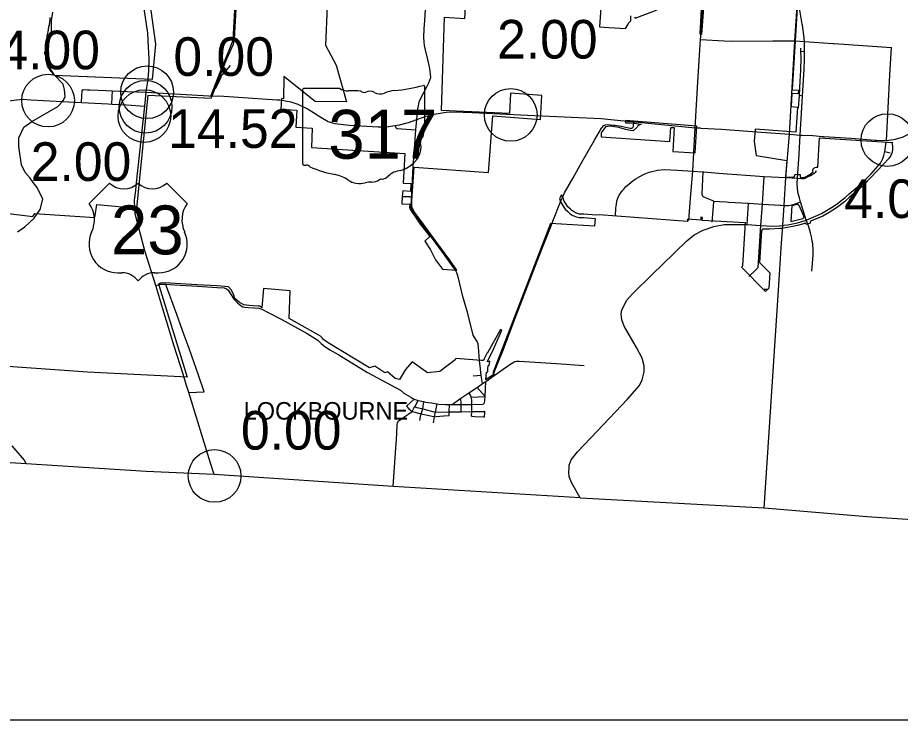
# Model space of a CAD drawing. Extents: x 1729596 to 1934326, y 644115 to 911751.
# Drawn here: x 1824362 to 1849496, y 650175 to 670183 of the extents above; entities that cross this region are included whole.
import ezdxf

# ---------------------------------------------------------------- set-up
doc = ezdxf.new("R2010")
doc.units = 0
for name, color, linetype in [('Default', 7, 'Continuous'), ('GM_X_City_Street', 7, 'Continuous'), ('GM_X_Corporation', 7, 'Continuous'), ('GM_X_Corporation_Text', 7, 'Continuous'), ('GM_X_County', 7, 'Continuous'), ('GM_X_County_Road', 7, 'Continuous'), ('GM_X_State_Route', 7, 'Continuous'), ('GM_X_State_Shield', 7, 'Continuous'), ('GM_X_Township', 7, 'Continuous'), ('GM_X_Township_Road', 7, 'Continuous'), ('GM_X_US_Route', 7, 'Continuous'), ('GM_X_US_Shield', 7, 'Continuous'), ('SC_Scratch1', 7, 'Continuous')]:
    doc.layers.add(name, color=color, linetype=linetype)

msp = doc.modelspace()

# ---------------------------------------------------------------- linework, layer by layer
at = {"layer": 'Default'}
for centre in [(1828047, 668059), (1825227, 667820), (1828004, 667646), (1827970, 667382), (1838401, 667414), (1849129, 666698), (1829970, 657133), (1829970, 657133)]:
    msp.add_circle(centre, 750, dxfattribs=at)
at = {"layer": 'GM_X_City_Street'}
for points in [[(1843656, 667049), (1843730, 668355), (1843808, 669565), (1843821, 669743)], [(1843808, 669565), (1844483, 669519), (1844695, 669514), (1845864, 669519), (1846450, 669518)], [(1846766, 669501), (1847577, 669446), (1847609, 669443)], [(1847609, 669443), (1849242, 669337)], [(1849099, 666688), (1849197, 668542), (1849242, 669337)], [(1839885, 665084), (1839885, 665085), (1839936, 665199), (1840176, 665624), (1840428, 666065), (1840789, 666690), (1840989, 667035), (1841055, 667112), (1841091, 667132), (1841160, 667140), (1841329, 667121)], [(1841329, 667121), (1841331, 667121), (1841362, 667118), (1841548, 667090), (1841804, 667034), (1841850, 667040), (1841888, 667054), (1841901, 667094), (1841906, 667217)], [(1846817, 664417), (1846817, 664417), (1846650, 664934), (1846620, 665052), (1846589, 665176), (1846576, 665245), (1846564, 665323), (1846559, 665448), (1846566, 665612), (1846612, 666291), (1846640, 666840)], [(1848969, 666119), (1848995, 666171), (1849029, 666256), (1849053, 666371), (1849069, 666502), (1849090, 666636)], [(1843475, 664407), (1843521, 665040), (1843585, 665813), (1843616, 666340), (1843616, 666350)], [(1849053, 666371), (1849205, 666333)], [(1847754, 664925), (1847924, 665066), (1848036, 665165), (1848377, 665454), (1848662, 665739), (1848862, 665965), (1848928, 666037), (1848969, 666119)], [(1841382, 664543), (1841399, 664762), (1841410, 664876), (1841424, 664962), (1841449, 665044), (1841489, 665125), (1841589, 665265), (1841622, 665300), (1841682, 665373), (1841763, 665445), (1841876, 665541), (1841950, 665588), (1842030, 665633), (1842044, 665642), (1842201, 665725), (1842346, 665782), (1842578, 665838), (1842779, 665860), (1843152, 665838), (1843585, 665813)], [(1843585, 665813), (1843884, 665790), (1843899, 665789)], [(1846566, 665612), (1846682, 665605), (1846753, 665606), (1846788, 665616), (1846809, 665625), (1846876, 665657), (1846937, 665690), (1846981, 665717), (1847038, 665750), (1847077, 665776), (1847110, 665825)], [(1844182, 664943), (1844183, 664956), (1843899, 665072), (1843876, 665090), (1843858, 665121), (1843856, 665165), (1843884, 665790)], [(1843899, 665789), (1844317, 665758)], [(1844317, 665758), (1845623, 665660), (1846239, 665629), (1846252, 665628)], [(1845180, 662812), (1845373, 662988), (1845449, 663072), (1845481, 663663), (1845515, 664119), (1845524, 664265), (1845568, 664872), (1845623, 665660)], [(1846252, 665628), (1846566, 665612)], [(1839549, 664258), (1839549, 664258), (1839599, 664384), (1839820, 664942), (1839841, 664989)], [(1844141, 664364), (1844165, 664687), (1844173, 664813), (1844182, 664943)], [(1844183, 664956), (1844349, 664944), (1844545, 664934)], [(1844545, 664934), (1844603, 664931), (1845177, 664896), (1845568, 664872), (1846075, 664842), (1846096, 664841)], [(1845136, 664293), (1845177, 664896)], [(1846096, 664841), (1846187, 664837), (1846309, 664831), (1846457, 664867), (1846650, 664934)], [(1846817, 664417), (1847083, 664527), (1847247, 664603), (1847588, 664806), (1847736, 664910), (1847754, 664925)], [(1846184, 664272), (1846281, 664286), (1846389, 664307), (1846430, 664315)], [(1846430, 664315), (1846528, 664335), (1846662, 664370), (1846817, 664417)], [(1846845, 664350), (1846817, 664417)], [(1845083, 664290), (1845136, 664289)], [(1845136, 664293), (1845524, 664265), (1845535, 664264)], [(1845535, 664264), (1845681, 664255), (1845825, 664250), (1846053, 664255), (1846149, 664267), (1846184, 664272)], [(1845481, 663663), (1845535, 663659)], [(1837539, 660181), (1837510, 660425), (1837488, 660804), (1837473, 660888), (1837445, 660962), (1837363, 661097), (1837334, 661143), (1837179, 661755), (1837041, 662240), (1836911, 662767)], [(1845621, 662454), (1845730, 662447)], [(1837596, 659765), (1837560, 659995), (1837541, 660163), (1837539, 660181)], [(1837560, 659995), (1837334, 659976)], [(1837635, 659187), (1837659, 659225), (1837665, 659283), (1837670, 659391), (1837689, 659827)], [(1835769, 659280), (1835932, 659249), (1835976, 659238), (1836143, 659213), (1836308, 659188), (1836352, 659181), (1836539, 659172), (1836658, 659169), (1836730, 659167), (1836917, 659304), (1836983, 659348), (1837212, 659501), (1837429, 659645), (1837445, 659656), (1837596, 659765)], [(1837670, 659391), (1837445, 659656)], [(1835149, 658156), (1835173, 658586), (1835178, 658644), (1835198, 658690), (1835228, 658716), (1835388, 658822), (1835503, 658898), (1835594, 658965), (1835647, 659068), (1835667, 659101), (1835765, 659280), (1835769, 659280)], [(1835431, 659119), (1835651, 659324)], [(1835571, 659367), (1835611, 659343), (1835651, 659324), (1835705, 659300), (1835765, 659280)], [(1836986, 659182), (1836986, 659182), (1836983, 659348)], [(1837293, 659205), (1837293, 659298), (1837275, 659375), (1837255, 659430), (1837212, 659501)], [(1837275, 659375), (1837670, 659391)], [(1835431, 659119), (1835501, 659049), (1835594, 658965)], [(1835667, 659101), (1835727, 659083), (1835872, 659050)], [(1835847, 658874), (1835854, 658904), (1835895, 659045), (1835932, 659249)], [(1835872, 659050), (1835895, 659045), (1836247, 658952), (1836260, 658952), (1836272, 658952), (1836650, 658957), (1836651, 658957)], [(1836244, 658873), (1836260, 658952), (1836308, 659188)], [(1836645, 658855), (1836650, 658957), (1836658, 659169)], [(1836730, 659167), (1836986, 659169), (1837283, 659172), (1837284, 659172)], [(1836990, 658961), (1836986, 659169), (1836986, 659182)], [(1837284, 659172), (1837293, 659172), (1837595, 659175), (1837635, 659187)], [(1837289, 658839), (1837291, 658965), (1837292, 659041), (1837293, 659172), (1837293, 659204), (1837293, 659205)], [(1835594, 658965), (1835854, 658904), (1836211, 658826), (1836233, 658821), (1836279, 658824)], [(1835811, 658713), (1835846, 658870), (1835847, 658874)], [(1836201, 658642), (1836233, 658821), (1836240, 658855), (1836244, 658873)], [(1836279, 658824), (1836489, 658841), (1836508, 658843)], [(1836508, 658843), (1836645, 658855)], [(1836651, 658957), (1836990, 658961), (1837283, 658965), (1837284, 658965)], [(1837284, 658965), (1837291, 658965), (1837654, 658970)], [(1837289, 658839), (1837307, 658831), (1837377, 658823), (1837627, 658812), (1837653, 658816)], [(1837653, 658816), (1837657, 658830), (1837666, 658934), (1837660, 658964), (1837654, 658970)]]:
    msp.add_lwpolyline(points, dxfattribs=at)
at = {"layer": 'GM_X_Corporation'}
for points in [[(1833173, 670502), (1833129, 669403), (1833432, 668828), (1833725, 667789), (1832832, 667797), (1831945, 668503), (1831927, 667875), (1831874, 667878), (1831856, 667578), (1832313, 667551), (1832283, 667067), (1832752, 667038), (1832725, 666484), (1835390, 666313), (1835341, 665474), (1835554, 665456), (1835544, 665236), (1835325, 665251), (1835312, 665101), (1835531, 665087), (1835531, 665067), (1835311, 665081), (1835298, 664882), (1835526, 664868), (1835524, 664780), (1835526, 664761), (1835534, 664732), (1835571, 664680), (1835694, 664503), (1835826, 664305), (1835933, 664158), (1836095, 663953), (1835954, 663820), (1836119, 663570), (1836264, 663286), (1836455, 663025), (1836867, 662988), (1836671, 663278), (1836402, 663637), (1836133, 663996), (1835831, 664420), (1835664, 664648), (1835602, 664750), (1835586, 664820), (1835588, 664971), (1835652, 665922), (1837770, 665776), (1837890, 667386), (1839249, 667283), (1839283, 667963), (1838398, 668037), (1838370, 667454), (1836435, 667543), (1836512, 670195), (1837091, 670161), (1837244, 672782)], [(1841095, 672208), (1840928, 669924), (1841193, 669907), (1841670, 669872), (1841733, 669978), (1841760, 670027), (1841820, 670091), (1841822, 670234)], [(1827964, 671763), (1828287, 669430), (1828195, 668421), (1825415, 668535), (1825343, 668623), (1825317, 668649), (1825215, 668803), (1825206, 668828), (1825206, 668854), (1825172, 668956), (1825164, 668982), (1825164, 669084), (1825138, 669161), (1825138, 669186), (1825164, 669263), (1825155, 669289), (1825155, 669340), (1825172, 669365), (1825172, 669442), (1825189, 669493), (1825189, 669587), (1825198, 669613), (1825198, 669664), (1825224, 669741), (1825232, 669775), (1825232, 669800), (1825241, 669826), (1825241, 669877), (1825249, 669903), (1825249, 669928), (1825266, 669980), (1825266, 670005), (1825275, 670031), (1825275, 670082), (1825283, 670107), (1825283, 670133), (1825292, 670159), (1825292, 670184)], [(1823170, 664722), (1824798, 664523), (1824853, 664602), (1826558, 664497), (1826621, 664858), (1827759, 664757), (1828076, 667971), (1829875, 667888), (1829895, 667927), (1829974, 668145), (1830178, 668652), (1830316, 669014), (1830507, 669429), (1830540, 669567), (1830589, 670604)], [(1843847, 670779), (1843787, 669720), (1843847, 669716), (1843911, 670587)], [(1846554, 670450), (1846417, 668127), (1846599, 668118), (1846591, 668018), (1846408, 668027), (1846388, 667649), (1846569, 667637), (1846519, 666923), (1845364, 667003), (1845334, 666654), (1845390, 666258), (1846262, 666117), (1846226, 665648), (1846429, 665637), (1846458, 665637), (1846476, 665647), (1846487, 665681), (1846501, 665723), (1846566, 665719), (1846641, 665713), (1846639, 665643), (1846659, 665639), (1846749, 665636), (1846781, 665639), (1846936, 665727), (1846970, 665757), (1847013, 665789), (1847006, 665816), (1847008, 665855), (1847017, 665876), (1847031, 665892), (1847060, 665918), (1847099, 665924), (1847145, 665922), (1847195, 666756), (1849281, 666631), (1849253, 666605), (1849260, 666581), (1849271, 666516), (1849274, 666421), (1849256, 666323), (1849213, 666237), (1849156, 666160), (1849019, 666011), (1848463, 665434), (1848266, 665254), (1848053, 665068), (1847902, 664940), (1847682, 664768), (1847473, 664636), (1847286, 664528), (1846969, 664400), (1846941, 664380), (1846930, 664356), (1846932, 664333), (1846828, 664294), (1846822, 664305), (1846817, 664311), (1846810, 664318), (1846799, 664324), (1846792, 664326), (1846785, 664328), (1846779, 664328), (1846774, 664328), (1846765, 664326), (1846671, 664296), (1846569, 664268), (1846435, 664236), (1846331, 664215), (1846230, 664198), (1846120, 664183), (1846064, 664177), (1845775, 664157), (1845598, 664164), (1845585, 664162), (1845573, 664158), (1845568, 664155), (1845564, 664152), (1845561, 664149), (1845557, 664145), (1845554, 664141), (1845551, 664136), (1845548, 664126), (1845547, 664117), (1845488, 663214), (1845782, 662915), (1845754, 662480), (1845654, 662382), (1844970, 663080), (1845008, 663118), (1845079, 664197), (1845091, 664343), (1843852, 664410), (1843858, 664495), (1843818, 664498), (1843812, 664413), (1843436, 664446), (1843431, 664380), (1840918, 664570), (1840821, 664563), (1840721, 664572), (1840594, 664579), (1840488, 664588), (1840362, 664591), (1840275, 664616), (1840185, 664659), (1840141, 664689), (1840100, 664731), (1840029, 664794), (1839982, 664868), (1839927, 664954), (1839900, 665013), (1839881, 665072), (1839849, 665140), (1839788, 665035), (1839807, 664976), (1839839, 664907), (1839897, 664814), (1839952, 664729), (1840031, 664659), (1840076, 664613), (1840134, 664572), (1840239, 664522), (1840346, 664491), (1840483, 664488), (1840587, 664479), (1840810, 664467), (1840791, 664246), (1839539, 664319), (1837903, 660085), (1837906, 660012), (1837693, 659866), (1837711, 660090), (1837749, 660096), (1837749, 660174), (1837758, 660274), (1837789, 660277), (1837806, 660397), (1837736, 660385), (1837737, 660406), (1837871, 660656), (1838144, 661289), (1838115, 661308), (1837739, 660642), (1837730, 660637), (1837650, 660468), (1837643, 660467), (1837628, 660417), (1837560, 660424), (1836841, 660477), (1836820, 660441), (1836379, 660107), (1836032, 660072), (1835600, 660381), (1835410, 660160), (1835235, 659876), (1835111, 659911), (1834892, 660102), (1834817, 660072), (1834534, 660260), (1834378, 660215), (1833202, 660924), (1833136, 660973), (1833080, 661013), (1833037, 661066), (1832988, 661115), (1832094, 661612), (1832122, 662401), (1831365, 662472), (1831316, 661924), (1831266, 661966), (1831214, 661966), (1831082, 661979), (1830950, 661986), (1830799, 662005), (1830674, 662084), (1830547, 662190), (1830509, 662306), (1830444, 662430), (1830367, 662519), (1830047, 662543), (1829462, 662573), (1829006, 662601), (1828560, 662630), (1828432, 662619), (1828372, 662605), (1828393, 662538), (1829185, 659944), (1829005, 659953), (1826346, 660092), (1823279, 660307)], [(1841925, 670207), (1841947, 670164), (1842571, 670405)]]:
    msp.add_lwpolyline(points, dxfattribs=at)
for points in [[(1840973, 666785), (1842934, 666660), (1842960, 667059), (1843060, 667053), (1843016, 666374), (1843655, 666333), (1843703, 667089), (1841673, 667256), (1841669, 667188), (1841791, 667188), (1841899, 667182), (1842117, 667152), (1842021, 667099), (1841998, 667063), (1841893, 666961), (1841814, 666971), (1841669, 666997), (1841482, 667051), (1841233, 667091), (1841099, 667071), (1840981, 666907)], [(1846404, 664824), (1846380, 664376), (1846715, 664465), (1846720, 664468), (1846727, 664471), (1846733, 664476), (1846738, 664482), (1846742, 664487), (1846746, 664494), (1846748, 664503), (1846749, 664509), (1846749, 664514), (1846749, 664518), (1846748, 664522), (1846746, 664530), (1846628, 664815), (1846599, 664849), (1846574, 664862), (1846538, 664862), (1846444, 664832)]]:
    msp.add_lwpolyline(points, close=True, dxfattribs=at)
at = {"layer": 'GM_X_County'}
msp.add_lwpolyline([(1864124, 654894), (1861474, 655088), (1858836, 655268), (1856984, 655410), (1856164, 655463), (1848544, 655971), (1845619, 656217), (1840391, 656502), (1840376, 656506), (1835058, 656829), (1829957, 657174), (1828024, 657258), (1824608, 657476), (1824149, 657505)], dxfattribs=at)
at = {"layer": 'GM_X_County_Road'}
for points in [[(1835726, 667283), (1835745, 667485), (1835757, 667591), (1835774, 667670), (1835786, 667727), (1835791, 667782), (1835839, 667894), (1836014, 668215), (1836071, 668330), (1836123, 668479), (1836116, 668587), (1836095, 668735), (1836041, 668994), (1835966, 669307), (1835946, 669390), (1835935, 669480), (1835928, 669628), (1835936, 669866), (1835956, 670105), (1836013, 671040), (1836074, 671915), (1836079, 671989)], [(1843821, 669743), (1843839, 669999), (1843883, 670657), (1843907, 671020), (1843934, 671139), (1844001, 671241), (1844363, 671669), (1844646, 671969), (1844716, 672019), (1844800, 672040), (1844936, 672044)], [(1846640, 666840), (1846708, 667950), (1846757, 668714), (1846771, 668977), (1846764, 669216), (1846767, 669366), (1846766, 669501), (1846747, 669685), (1846707, 669967), (1846704, 669999), (1846624, 670451), (1846576, 670629)], [(1829863, 667951), (1830197, 668799), (1830241, 668908), (1830480, 669493), (1830494, 669553), (1830533, 670220), (1830559, 670575)], [(1846450, 669518), (1846495, 669518), (1846766, 669501)], [(1836911, 662767), (1836888, 662861), (1836869, 662917), (1836825, 662989), (1836770, 663073), (1836484, 663471), (1836120, 663970), (1835630, 664655), (1835599, 664703), (1835570, 664765), (1835565, 664835), (1835627, 665925), (1835704, 666993), (1835726, 667283)], [(1843616, 666350), (1843656, 667049)], [(1846975, 662962), (1846993, 663178), (1847000, 663303), (1847015, 663425), (1847017, 663562), (1847000, 663747), (1846989, 663832), (1846965, 663942), (1846939, 664055), (1846911, 664156), (1846862, 664309), (1846845, 664350)], [(1840376, 656506), (1840141, 656930), (1840067, 657109), (1840057, 657242), (1840063, 657371), (1840066, 657440), (1840122, 657591), (1840303, 657819), (1840863, 658408), (1841726, 659318), (1842067, 659709), (1842146, 659870), (1842197, 660101), (1842198, 660267), (1842141, 660487), (1841983, 660787), (1841632, 661394), (1841565, 661580), (1841544, 661748), (1841567, 661856), (1841702, 662132), (1841862, 662314), (1842441, 662882), (1842721, 663156), (1843415, 663830), (1843630, 663997), (1843886, 664136), (1844189, 664240), (1844480, 664290), (1844761, 664295), (1845083, 664290)], [(1828294, 662557), (1828371, 662577), (1828435, 662590), (1828496, 662595), (1828579, 662591), (1828829, 662578), (1829486, 662536), (1830044, 662503), (1830245, 662491), (1830309, 662465), (1830356, 662424), (1830426, 662316), (1830531, 662162), (1830624, 662058), (1830727, 661977), (1830773, 661950), (1830827, 661936), (1830921, 661925), (1831094, 661920), (1831232, 661911), (1831312, 661884), (1831499, 661792), (1831864, 661593), (1832604, 661189), (1832910, 661004), (1833003, 660903), (1833067, 660844), (1833248, 660727), (1833505, 660578), (1834323, 660083), (1835259, 659572), (1835355, 659495), (1835561, 659373), (1835571, 659367)], [(1837596, 659765), (1837689, 659827), (1837933, 659996), (1838379, 660303), (1838454, 660350), (1838502, 660378), (1838533, 660390), (1838570, 660400), (1838607, 660404), (1838642, 660404), (1839710, 660331), (1840491, 660277)], [(1835058, 656829), (1835144, 658069), (1835149, 658156)]]:
    msp.add_lwpolyline(points, dxfattribs=at)
at = {"layer": 'GM_X_State_Route'}
for points in [[(1848819, 666696), (1849099, 666688), (1849232, 666701), (1849354, 666722), (1849455, 666750), (1849554, 666780), (1849673, 666832), (1849786, 666895), (1850303, 667340), (1851168, 668195), (1852000, 669022), (1852811, 669805), (1853162, 670133), (1853612, 670573), (1854310, 671256), (1854583, 671527)], [(1822891, 667232), (1822862, 667499), (1822856, 667582), (1822875, 667625), (1822910, 667656), (1822955, 667668), (1823148, 667696), (1823266, 667709), (1823461, 667737), (1824045, 667809), (1824325, 667846), (1824516, 667859), (1824733, 667846)], [(1824733, 667846), (1825638, 667792), (1826177, 667769), (1826941, 667726), (1827041, 667721), (1827462, 667696), (1827982, 667658)], [(1828023, 668059), (1829809, 667955)], [(1829809, 667955), (1829863, 667951)], [(1829863, 667951), (1830093, 667953), (1830229, 667944), (1830231, 667944)], [(1830231, 667944), (1831755, 667844)], [(1831755, 667844), (1831757, 667844), (1831841, 667839), (1832141, 667785), (1832339, 667720), (1832635, 667581), (1832995, 667345), (1833203, 667226), (1833395, 667167), (1833809, 667122), (1834631, 667072), (1834871, 667077), (1835099, 667108), (1835239, 667134), (1835488, 667199), (1835726, 667283), (1835995, 667379), (1836110, 667408), (1836218, 667432), (1836336, 667454), (1836453, 667475), (1836566, 667490), (1836794, 667502), (1837305, 667480), (1839076, 667399)], [(1839076, 667399), (1840981, 667311), (1841906, 667217), (1842026, 667205)], [(1842026, 667205), (1843656, 667049), (1843791, 667041), (1843813, 667039)], [(1843813, 667039), (1844404, 667003), (1845537, 666925), (1845541, 666925)], [(1845541, 666925), (1846337, 666862), (1846640, 666840), (1846696, 666838)], [(1846696, 666838), (1847007, 666825), (1847282, 666803), (1847311, 666801)], [(1847311, 666801), (1848096, 666749), (1848769, 666698), (1848819, 666696)]]:
    msp.add_lwpolyline(points, dxfattribs=at)
at = {"layer": 'GM_X_State_Shield'}
for p, q in [((1832477, 668130), (1832477, 666017)), ((1833531, 668166), (1832512, 668166)), ((1835958, 667113), (1835958, 668219)), ((1835958, 667113), (1835958, 667113))]:
    msp.add_line(p, q, dxfattribs=at)
for centre, major_axis, start_param, end_param in [((1832517, 668134), (40.3, 0), 1.712693, 3.28349), ((1833774, 668412), (391, 0), 4.042523, 4.731795), ((1833903, 666980), (1404, 0), 1.404758, 1.657858), ((1834222, 668145), (113, 0), 3.836095, 5.185415), ((1834388, 667901), (235, 0), 0.950623, 2.079405), ((1835189, 667521), (743, 0), 1.699011, 2.107814), ((1834718, 671047), (3691, 0), 4.814394, 5.042369), ((1835919, 668223), (38.7, 0), 6.141152, 7.989035), ((1834691, 668236), (282, 0), 4.081561, 5.145723), ((1835949, 667032), (60, 0), 1.883978, 3.671073), ((1835917, 667109), (41.5, 0), 5.05454, 6.418171), ((1835567, 666892), (360, 0), 5.934695, 6.695948), ((1834925, 666510), (923, 0), 5.101752, 6.440018), ((1836097, 666651), (262, 0), 2.387724, 3.262537), ((1832518, 666012), (40.7, 0), 3.00124, 4.508301), ((1832524, 666228), (310, 0), 4.665946, 4.897461), ((1832587, 665895), (112, 0), 0.519207, 1.627899), ((1834001, 667793), (2665, 0), 4.195997, 4.488961), ((1835314, 665423), (506, 0), 1.647645, 2.488434), ((1833206, 665067), (834, 0), 0.823519, 1.323587), ((1834452, 665726), (282, 0), 4.691044, 5.507374), ((1834707, 665521), (79.4, 0), 1.147584, 2.315152), ((1834674, 665812), (298, 0), 4.937069, 5.64225), ((1834108, 665884), (529, 0), 4.026481, 4.996735), ((1834414, 665154), (435, 0), 1.495662, 1.94098)]:
    msp.add_ellipse(centre, major_axis=major_axis, ratio=0.8, start_param=start_param, end_param=end_param, dxfattribs=at)
at = {"layer": 'GM_X_Township'}
for points in [[(1845619, 656217), (1846028, 662425), (1846067, 663021), (1846107, 663627), (1846149, 664267), (1846187, 664837), (1846239, 665629), (1846337, 666862), (1846495, 669518), (1846570, 670652)], [(1824354, 664086), (1824570, 664230), (1824832, 664475), (1824999, 664717), (1825079, 665016), (1824920, 665350), (1824801, 665486), (1824719, 665616), (1824573, 665774), (1824475, 665996), (1824395, 666511), (1824394, 666764), (1824537, 667061), (1824767, 667223), (1825502, 667657), (1825638, 667792), (1825659, 667828), (1825710, 667930), (1825695, 668141), (1825653, 668286), (1825410, 668543), (1825260, 668778), (1825198, 669095), (1825211, 669407), (1825284, 669603), (1825321, 669802), (1825324, 670099), (1825363, 670338)], [(1824608, 657476), (1824553, 657587), (1824209, 657995)]]:
    msp.add_lwpolyline(points, dxfattribs=at)
at = {"layer": 'GM_X_Township_Road'}
for points in [[(1846597, 667605), (1846620, 667964), (1846641, 668374), (1846658, 668681), (1846676, 669048), (1846667, 669226), (1846667, 669230), (1846666, 669254)], [(1846666, 669254), (1846665, 669310)], [(1846672, 669225), (1846764, 669216)], [(1829999, 668168), (1830106, 668384), (1830157, 668502), (1830180, 668550), (1830212, 668584), (1830279, 668655), (1830315, 668693), (1830329, 668709), (1830426, 668822)], [(1830197, 668799), (1830315, 668693)], [(1826177, 667769), (1826186, 667964), (1826188, 667987), (1826194, 668060), (1826198, 668098), (1826213, 668126), (1826214, 668127)], [(1826214, 668127), (1826224, 668131), (1826229, 668134), (1826351, 668132), (1826415, 668130), (1826885, 668109), (1827040, 668102)], [(1827040, 668102), (1827065, 668100), (1827480, 668083), (1828023, 668059)], [(1827041, 667721), (1827054, 667926), (1827065, 668100)], [(1846708, 667950), (1846620, 667964)], [(1835099, 667108), (1835133, 667058), (1835169, 667031), (1835704, 666993)], [(1839841, 664989), (1839842, 664989), (1839885, 665084)], [(1837933, 659996), (1837926, 660034), (1837925, 660057), (1837927, 660080), (1837945, 660136), (1838168, 660669), (1838530, 661624), (1839037, 662959), (1839283, 663593), (1839549, 664258)], [(1829232, 659510), (1829676, 659525), (1829509, 659999), (1829241, 660767), (1829107, 661146), (1828893, 661733), (1828685, 662298), (1828611, 662499), (1828579, 662591)]]:
    msp.add_lwpolyline(points, dxfattribs=at)
at = {"layer": 'GM_X_US_Route'}
for points in [[(1828076, 668424), (1828078, 668435), (1828095, 668678), (1828104, 668988), (1828098, 669186), (1828089, 669347), (1828064, 669738), (1827942, 670571), (1827843, 671337), (1827713, 672459), (1827600, 673434), (1827337, 675491), (1827070, 677598), (1826976, 678448), (1826931, 678843), (1826719, 680703), (1826701, 680872)], [(1828023, 668059), (1828042, 668195), (1828076, 668424)], [(1827982, 667658), (1828000, 667862), (1828023, 668059)], [(1827737, 665390), (1827794, 665914), (1827876, 666700), (1827982, 667658)], [(1827702, 664755), (1827693, 664982), (1827723, 665265), (1827736, 665386), (1827737, 665390)], [(1828294, 662557), (1827986, 663547), (1827708, 664593), (1827702, 664755)], [(1829162, 659739), (1829073, 660032), (1828822, 660833), (1828496, 661890), (1828294, 662557)], [(1829957, 657174), (1829856, 657499), (1829232, 659510), (1829162, 659739)]]:
    msp.add_lwpolyline(points, dxfattribs=at)
at = {"layer": 'GM_X_US_Shield'}
for p, q in [((1826981, 665473), (1826401, 664893)), ((1829185, 664893), (1828605, 665473)), ((1827213, 662921), (1827329, 662921)), ((1828257, 662921), (1828373, 662921))]:
    msp.add_line(p, q, dxfattribs=at)
for centre, radius, start, end in [((1827387, 665887), 580, 225.573, 314.427), ((1828199, 665887), 580, 225.573, 314.427), ((1825736, 664427), 812, 334.5471, 35.0009), ((1829851, 664427), 812, 144.9991, 205.4529), ((1827204, 663733), 812, 154.8319, 270.6383), ((1828382, 663733), 812, 269.3617, 25.1681), ((1827329, 662341), 580, 36.8699, 90), ((1828257, 662341), 580, 90, 143.1301)]:
    msp.add_arc(centre, radius, start, end, dxfattribs=at)
at = {"layer": 'SC_Scratch1'}
msp.add_lwpolyline([(1730291, 784675), (1926541, 784675), (1926541, 650175), (1730291, 650175)], close=True, dxfattribs=at)

# ---------------------------------------------------------------- texts
at = {"layer": 'Default'}
for s, p in [('2.00', (1838013, 669018)), ('14.00', (1823024, 668713)), ('0.00', (1828797, 668524)), ('14.52', (1828648, 666474)), ('2.00', (1824735, 665534)), ('4.00', (1847899, 664477)), ('0.00', (1830720, 657883))]:
    msp.add_text(s, height=1100, dxfattribs=at).set_placement(p)
at = {"layer": 'GM_X_Corporation_Text'}
msp.add_text('LOCKBOURNE', height=500, rotation=0, dxfattribs=at).set_placement((1830798, 658737))
at = {"layer": 'GM_X_State_Shield'}
msp.add_text('317', height=1392.2, dxfattribs=at).set_placement((1833207, 666166))
at = {"layer": 'GM_X_US_Shield'}
msp.add_text('23', height=1392.2, dxfattribs=at).set_placement((1827018, 663443))

doc.saveas('drawing.dxf')
